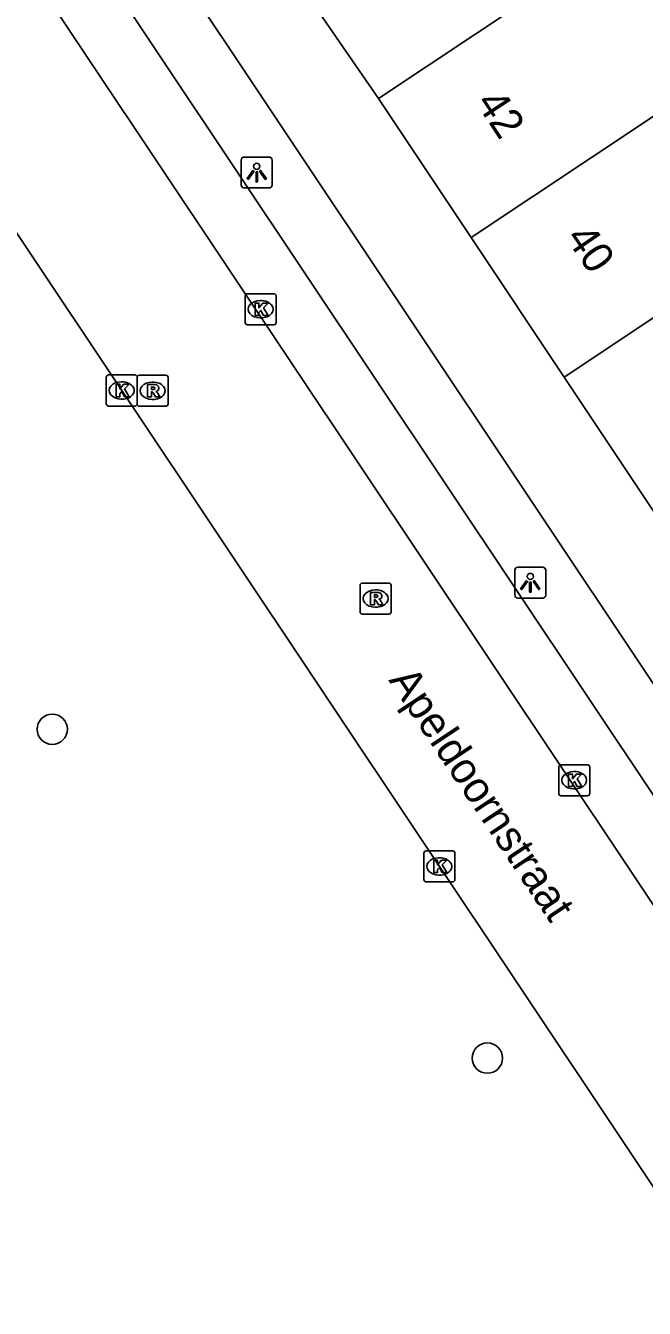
# Model space of a CAD drawing. Extents: x 158352 to 159489, y 383828 to 384597.
# Drawn here: x 158665.59 to 158685.53, y 384250.69 to 384292.05 of the extents above; entities that cross this region are included whole.
import ezdxf

# ---------------------------------------------------------------- set-up
doc = ezdxf.new("R2010")
doc.units = 0
for name, color, linetype in [('IMGEO_Boom', 7, 'Continuous'), ('IMGEO_Kolk', 7, 'Continuous'), ('IMGEO_Lichtpunt', 7, 'Continuous'), ('IMGEO_Openbare_ruimte_label', 7, 'Continuous'), ('IMGEO_Pand', 7, 'Continuous'), ('IMGEO_Pand_nummerreeks', 7, 'Continuous'), ('IMGEO_Rijbaan_lokaal_open', 7, 'Continuous'), ('IMGEO_Rioolput', 7, 'Continuous'), ('IMGEO_Voetpad_open', 7, 'Continuous')]:
    doc.layers.add(name, color=color, linetype=linetype)

msp = doc.modelspace()

# ---------------------------------------------------------------- linework, layer by layer
at = {"layer": 'IMGEO_Boom'}
for centre in [(158666.45, 384269.362), (158680.469, 384258.759)]:
    msp.add_circle(centre, 0.489, dxfattribs=at)
at = {"layer": 'IMGEO_Kolk'}
for p, q in [((158672.664, 384282.477), (158672.664, 384283.329)), ((158672.739, 384283.403), (158673.591, 384283.403)), ((158673.665, 384283.329), (158673.665, 384282.477)), ((158673.152, 384283.183), (158673.177, 384283.183)), ((158673.175, 384282.623), (158673.15, 384282.623)), ((158673.591, 384282.403), (158672.739, 384282.403)), ((158668.261, 384280.784), (158669.113, 384280.784)), ((158668.186, 384279.858), (158668.186, 384280.71)), ((158668.674, 384280.564), (158668.699, 384280.564)), ((158669.187, 384280.71), (158669.187, 384279.858)), ((158668.697, 384280.004), (158668.672, 384280.004)), ((158669.113, 384279.784), (158668.261, 384279.784)), ((158682.766, 384267.293), (158682.766, 384268.145)), ((158682.841, 384268.219), (158683.693, 384268.219)), ((158683.254, 384267.999), (158683.279, 384267.999)), ((158683.767, 384268.145), (158683.767, 384267.293)), ((158683.693, 384267.219), (158682.841, 384267.219)), ((158683.277, 384267.439), (158683.252, 384267.439)), ((158678.421, 384264.513), (158678.421, 384265.365)), ((158678.496, 384265.439), (158679.348, 384265.439)), ((158678.909, 384265.219), (158678.934, 384265.219)), ((158679.422, 384265.365), (158679.422, 384264.513)), ((158678.932, 384264.659), (158678.907, 384264.659)), ((158679.348, 384264.439), (158678.496, 384264.439))]:
    msp.add_line(p, q, dxfattribs=at)
for points in [[(158672.664, 384282.477), (158672.664, 384283.329)], [(158672.739, 384283.403), (158673.591, 384283.403)], [(158673.665, 384283.329), (158673.665, 384282.477)], [(158672.985, 384283.103), (158673.108, 384283.103), (158673.108, 384282.952), (158673.238, 384283.103), (158673.402, 384283.103), (158673.256, 384282.952), (158673.409, 384282.703), (158673.257, 384282.703), (158673.172, 384282.867), (158673.108, 384282.8), (158673.108, 384282.703), (158672.985, 384282.703), (158672.985, 384283.103)], [(158673.591, 384282.403), (158672.739, 384282.403)], [(158668.261, 384280.784), (158669.113, 384280.784)], [(158668.186, 384279.858), (158668.186, 384280.71)], [(158668.507, 384280.484), (158668.63, 384280.484), (158668.63, 384280.333), (158668.76, 384280.484), (158668.924, 384280.484), (158668.778, 384280.333), (158668.931, 384280.084), (158668.779, 384280.084), (158668.694, 384280.248), (158668.63, 384280.181), (158668.63, 384280.084), (158668.507, 384280.084), (158668.507, 384280.484)], [(158669.187, 384280.71), (158669.187, 384279.858)], [(158669.113, 384279.784), (158668.261, 384279.784)], [(158682.766, 384267.293), (158682.766, 384268.145)], [(158682.841, 384268.219), (158683.693, 384268.219)], [(158683.767, 384268.145), (158683.767, 384267.293)], [(158683.087, 384267.919), (158683.21, 384267.919), (158683.21, 384267.768), (158683.34, 384267.919), (158683.504, 384267.919), (158683.358, 384267.768), (158683.511, 384267.519), (158683.359, 384267.519), (158683.274, 384267.683), (158683.21, 384267.616), (158683.21, 384267.519), (158683.087, 384267.519), (158683.087, 384267.919)], [(158683.693, 384267.219), (158682.841, 384267.219)], [(158678.421, 384264.513), (158678.421, 384265.365)], [(158678.496, 384265.439), (158679.348, 384265.439)], [(158678.742, 384265.139), (158678.865, 384265.139), (158678.865, 384264.988), (158678.995, 384265.139), (158679.159, 384265.139), (158679.013, 384264.988), (158679.166, 384264.739), (158679.014, 384264.739), (158678.929, 384264.903), (158678.865, 384264.836), (158678.865, 384264.739), (158678.742, 384264.739), (158678.742, 384265.139)], [(158679.422, 384265.365), (158679.422, 384264.513)], [(158679.348, 384264.439), (158678.496, 384264.439)]]:
    msp.add_lwpolyline(points, dxfattribs=at)
for centre, start, end in [((158672.741, 384283.327), 91.552, 178.448), ((158672.741, 384283.327), 91.552, 178.448), ((158673.589, 384283.327), 1.552, 88.448), ((158673.589, 384283.327), 1.552, 88.448), ((158672.741, 384282.479), 181.552, 268.448), ((158672.741, 384282.479), 181.552, 268.448), ((158673.589, 384282.479), 271.552, 358.448), ((158673.589, 384282.479), 271.552, 358.448), ((158668.263, 384280.708), 91.552, 178.448), ((158668.263, 384280.708), 91.552, 178.448), ((158669.111, 384280.708), 1.552, 88.448), ((158669.111, 384280.708), 1.552, 88.448), ((158668.263, 384279.86), 181.552, 268.448), ((158668.263, 384279.86), 181.552, 268.448), ((158669.111, 384279.86), 271.552, 358.448), ((158669.111, 384279.86), 271.552, 358.448), ((158682.843, 384268.143), 91.552, 178.448), ((158682.843, 384268.143), 91.552, 178.448), ((158683.691, 384268.143), 1.552, 88.448), ((158683.691, 384268.143), 1.552, 88.448), ((158682.843, 384267.295), 181.552, 268.448), ((158682.843, 384267.295), 181.552, 268.448), ((158683.691, 384267.295), 271.552, 358.448), ((158683.691, 384267.295), 271.552, 358.448), ((158678.498, 384265.363), 91.552, 178.448), ((158678.498, 384265.363), 91.552, 178.448), ((158679.346, 384265.363), 1.552, 88.448), ((158679.346, 384265.363), 1.552, 88.448), ((158678.498, 384264.515), 181.552, 268.448), ((158678.498, 384264.515), 181.552, 268.448), ((158679.346, 384264.515), 271.552, 358.448), ((158679.346, 384264.515), 271.552, 358.448)]:
    msp.add_arc(centre, 0.0765, start, end, dxfattribs=at)
for centre, major_axis, ratio, start_param, end_param in [((158673.151, 384282.903), (-0.387, 0.002), 0.722429, 4.712389, 7.853982), ((158673.176, 384282.903), (-0.39, 0.002), 0.717154, 1.570796, 4.712389), ((158668.673, 384280.284), (-0.387, 0.002), 0.722429, 4.712389, 7.853982), ((158668.698, 384280.284), (-0.39, 0.002), 0.717154, 1.570796, 4.712389), ((158683.253, 384267.719), (-0.387, 0.002), 0.722429, 4.712389, 7.853982), ((158683.278, 384267.719), (-0.39, 0.002), 0.717154, 1.570796, 4.712389), ((158678.908, 384264.939), (-0.387, 0.002), 0.722429, 4.712389, 7.853982), ((158678.933, 384264.939), (-0.39, 0.002), 0.717154, 1.570796, 4.712389)]:
    msp.add_ellipse(centre, major_axis=major_axis, ratio=ratio, start_param=start_param, end_param=end_param, dxfattribs=at)
at = {"layer": 'IMGEO_Lichtpunt'}
for p, q in [((158673.441, 384287.81), (158672.633, 384287.81)), ((158673.441, 384287.81), (158672.633, 384287.81)), ((158672.539, 384287.715), (158672.539, 384286.908)), ((158672.539, 384287.715), (158672.539, 384286.908)), ((158673.535, 384286.908), (158673.535, 384287.715)), ((158673.535, 384286.908), (158673.535, 384287.715)), ((158672.633, 384286.814), (158673.441, 384286.814)), ((158672.633, 384286.814), (158673.441, 384286.814)), ((158682.255, 384274.585), (158681.447, 384274.585)), ((158682.255, 384274.585), (158681.447, 384274.585)), ((158681.353, 384274.49), (158681.353, 384273.683)), ((158681.353, 384274.49), (158681.353, 384273.683)), ((158682.349, 384273.683), (158682.349, 384274.49)), ((158682.349, 384273.683), (158682.349, 384274.49)), ((158681.447, 384273.589), (158682.255, 384273.589)), ((158681.447, 384273.589), (158682.255, 384273.589))]:
    msp.add_line(p, q, dxfattribs=at)
for points in [[(158672.913, 384287.379), (158672.952, 384287.351), (158672.764, 384287.089), (158672.726, 384287.116), (158672.913, 384287.379)], [(158673.015, 384287.331), (158673.062, 384287.331), (158673.062, 384287.009), (158673.015, 384287.009), (158673.015, 384287.331)], [(158673.125, 384287.351), (158673.163, 384287.378), (158673.35, 384287.116), (158673.311, 384287.088), (158673.125, 384287.351)], [(158681.727, 384274.154), (158681.766, 384274.126), (158681.578, 384273.864), (158681.54, 384273.891), (158681.727, 384274.154)], [(158681.939, 384274.126), (158681.977, 384274.153), (158682.164, 384273.891), (158682.125, 384273.863), (158681.939, 384274.126)], [(158681.829, 384274.106), (158681.876, 384274.106), (158681.876, 384273.784), (158681.829, 384273.784), (158681.829, 384274.106)]]:
    msp.add_lwpolyline(points, dxfattribs=at)
for centre in [(158673.038, 384287.513), (158681.852, 384274.288)]:
    msp.add_circle(centre, 0.0994, dxfattribs=at)
for centre, start, end in [((158672.633, 384287.715), 90, 180), ((158672.633, 384287.715), 90, 180), ((158673.441, 384287.715), 0, 90), ((158673.441, 384287.715), 0, 90), ((158672.633, 384286.908), 180, 270), ((158672.633, 384286.908), 180, 270), ((158673.441, 384286.908), 270, 0), ((158673.441, 384286.908), 270, 360), ((158681.447, 384274.49), 90, 180), ((158681.447, 384274.49), 90, 180), ((158682.255, 384274.49), 0, 90), ((158682.255, 384274.49), 0, 90), ((158681.447, 384273.683), 180, 270), ((158681.447, 384273.683), 180, 270), ((158682.255, 384273.683), 270, 0), ((158682.255, 384273.683), 270, 360)]:
    msp.add_arc(centre, 0.0946, start, end, dxfattribs=at)
at = {"layer": 'IMGEO_Pand'}
for points in [[(158684.797, 384294.918), (158676.958, 384289.696)], [(158673.9, 384294.152), (158676.958, 384289.696)], [(158679.946, 384285.214), (158687.761, 384290.42)], [(158676.958, 384289.696), (158679.946, 384285.214)], [(158682.944, 384280.716), (158690.784, 384285.939)], [(158679.946, 384285.214), (158682.944, 384280.716)], [(158682.944, 384280.716), (158685.932, 384276.235)]]:
    msp.add_lwpolyline(points, dxfattribs=at)
at = {"layer": 'IMGEO_Rijbaan_lokaal_open'}
for points in [[(158693.594, 384252.04), (158659.086, 384303.74)], [(158654.177, 384302.038), (158655.789, 384299.623), (158691.316, 384246.356)]]:
    msp.add_lwpolyline(points, dxfattribs=at)
at = {"layer": 'IMGEO_Rioolput'}
for p, q in [((158669.258, 384280.776), (158670.11, 384280.776)), ((158669.183, 384279.85), (158669.183, 384280.702)), ((158669.671, 384280.556), (158669.696, 384280.556)), ((158670.184, 384280.702), (158670.184, 384279.85)), ((158669.694, 384279.996), (158669.669, 384279.996)), ((158670.11, 384279.776), (158669.258, 384279.776)), ((158676.368, 384273.149), (158676.368, 384274.001)), ((158676.443, 384274.075), (158677.295, 384274.075)), ((158676.856, 384273.855), (158676.881, 384273.855)), ((158677.369, 384274.001), (158677.369, 384273.149)), ((158677.295, 384273.075), (158676.443, 384273.075)), ((158676.879, 384273.295), (158676.854, 384273.295))]:
    msp.add_line(p, q, dxfattribs=at)
for points in [[(158669.258, 384280.776), (158670.11, 384280.776)], [(158669.183, 384279.85), (158669.183, 384280.702)], [(158669.772, 384280.474), (158669.52, 384280.476), (158669.52, 384280.076)], [(158669.698, 384280.395), (158669.644, 384280.395), (158669.644, 384280.314)], [(158670.184, 384280.702), (158670.184, 384279.85)], [(158669.52, 384280.076), (158669.644, 384280.076), (158669.644, 384280.238), (158669.655, 384280.238)], [(158669.644, 384280.314), (158669.696, 384280.314)], [(158669.702, 384280.209), (158669.773, 384280.076), (158669.913, 384280.076), (158669.848, 384280.202)], [(158670.11, 384279.776), (158669.258, 384279.776)], [(158676.368, 384273.149), (158676.368, 384274.001)], [(158676.443, 384274.075), (158677.295, 384274.075)], [(158676.957, 384273.773), (158676.705, 384273.775), (158676.705, 384273.375)], [(158677.369, 384274.001), (158677.369, 384273.149)], [(158676.705, 384273.375), (158676.829, 384273.375), (158676.829, 384273.537), (158676.84, 384273.537)], [(158676.883, 384273.694), (158676.829, 384273.694), (158676.829, 384273.613)], [(158676.829, 384273.613), (158676.881, 384273.613)], [(158676.887, 384273.508), (158676.958, 384273.375), (158677.098, 384273.375), (158677.033, 384273.501)], [(158677.295, 384273.075), (158676.443, 384273.075)]]:
    msp.add_lwpolyline(points, dxfattribs=at)
for centre, radius, start, end in [((158669.26, 384280.7), 0.0765, 91.552, 178.448), ((158669.26, 384280.7), 0.0765, 91.552, 178.448), ((158670.108, 384280.7), 0.0765, 1.552, 88.448), ((158670.108, 384280.7), 0.0765, 1.552, 88.448), ((158669.704, 384280.299), 0.0964, 77.0061, 93.1865), ((158669.718, 384280.356), 0.0378, 276.6634, 79.6772), ((158669.771, 384280.364), 0.109, 350.3612, 89.416), ((158669.654, 384280.185), 0.0533, 26.0293, 88.6989), ((158669.68, 384280.503), 0.19, 274.7715, 282.9687), ((158669.769, 384280.364), 0.112, 277.5842, 350.9817), ((158669.753, 384280.149), 0.108, 29.5134, 73.7905), ((158669.26, 384279.852), 0.0765, 181.552, 268.448), ((158669.26, 384279.852), 0.0765, 181.552, 268.448), ((158670.108, 384279.852), 0.0765, 271.552, 358.448), ((158670.108, 384279.852), 0.0765, 271.552, 358.448), ((158676.445, 384273.999), 0.0765, 91.552, 178.448), ((158676.445, 384273.999), 0.0765, 91.552, 178.448), ((158676.956, 384273.663), 0.109, 350.3612, 89.416), ((158677.293, 384273.999), 0.0765, 1.552, 88.448), ((158677.293, 384273.999), 0.0765, 1.552, 88.448), ((158676.839, 384273.484), 0.0533, 26.0293, 88.6989), ((158676.865, 384273.802), 0.19, 274.7715, 282.9687), ((158676.889, 384273.598), 0.0964, 77.0061, 93.1865), ((158676.903, 384273.655), 0.0378, 276.6634, 79.6772), ((158676.954, 384273.663), 0.112, 277.5842, 350.9817), ((158676.938, 384273.448), 0.108, 29.5134, 73.7905), ((158676.445, 384273.151), 0.0765, 181.552, 268.448), ((158676.445, 384273.151), 0.0765, 181.552, 268.448), ((158677.293, 384273.151), 0.0765, 271.552, 358.448), ((158677.293, 384273.151), 0.0765, 271.552, 358.448)]:
    msp.add_arc(centre, radius, start, end, dxfattribs=at)
for centre, major_axis, ratio, start_param, end_param in [((158669.67, 384280.276), (-0.387, 0.002), 0.722429, 4.712389, 7.853982), ((158669.695, 384280.276), (-0.39, 0.002), 0.717154, 1.570796, 4.712389), ((158676.855, 384273.575), (-0.387, 0.002), 0.722429, 4.712389, 7.853982), ((158676.88, 384273.575), (-0.39, 0.002), 0.717154, 1.570796, 4.712389)]:
    msp.add_ellipse(centre, major_axis=major_axis, ratio=ratio, start_param=start_param, end_param=end_param, dxfattribs=at)
at = {"layer": 'IMGEO_Voetpad_open'}
for points in [[(158661.89, 384306.702), (158737.694, 384193.032)], [(158693.763, 384252.543), (158695.03, 384253.434), (158660.956, 384304.482), (158659.679, 384303.634)]]:
    msp.add_lwpolyline(points, dxfattribs=at)

# ---------------------------------------------------------------- texts
at = {"layer": 'IMGEO_Openbare_ruimte_label'}
msp.add_text('Apeldoornstraat', height=1, rotation=303.706, dxfattribs=at).set_placement((158677.269, 384270.945))
at = {"layer": 'IMGEO_Pand_nummerreeks'}
for s, rotation, p in [('42', 303.3694, (158680.076, 384289.563)), ('40', 304.4434, (158682.967, 384285.207))]:
    msp.add_text(s, height=1, rotation=rotation, dxfattribs=at).set_placement(p)

doc.saveas('drawing.dxf')
